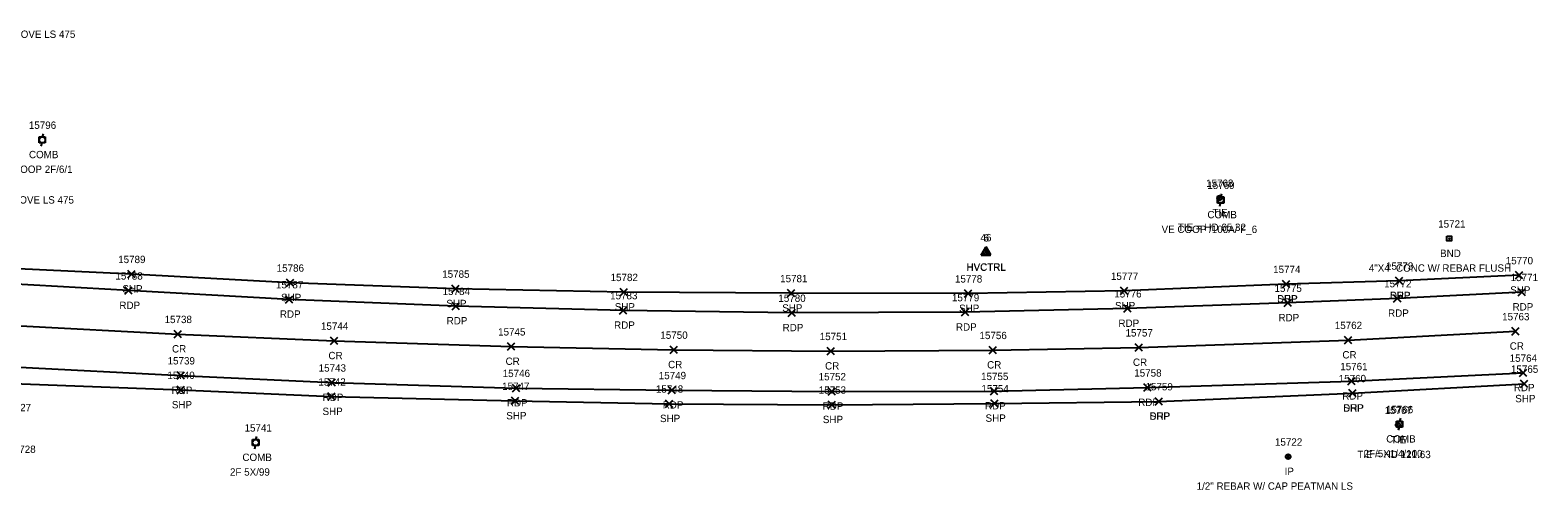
# Model space of a CAD drawing. Extents: x 1606530 to 1613020, y 784959 to 789666.
# Drawn here: x 1609686.4 to 1610096.8, y 788384.4 to 788509.5 of the extents above; entities that cross this region are included whole.
import ezdxf

# ---------------------------------------------------------------- set-up
doc = ezdxf.new("R2010")
doc.units = 0
for name, color, linetype in [('C_A', 7, 'Continuous'), ('C_C', 7, 'Continuous'), ('C_I', 7, 'Continuous'), ('CBP', 7, 'Continuous'), ('CPSM', 7, 'Continuous'), ('L_I', 7, 'Continuous'), ('M_A', 7, 'Continuous'), ('M_C', 7, 'Continuous'), ('M_I', 7, 'Continuous'), ('MHBP', 7, 'Continuous'), ('MPIR', 7, 'Continuous'), ('P_A', 7, 'Continuous'), ('P_I', 7, 'Continuous'), ('P_TIC', 7, 'Continuous'), ('PET', 7, 'Continuous'), ('PRC', 7, 'Continuous'), ('PSP', 7, 'Continuous'), ('R_A', 7, 'Continuous'), ('R_I', 7, 'Continuous'), ('R_TIC', 7, 'Continuous'), ('U_A', 7, 'Continuous'), ('U_C', 7, 'Continuous'), ('U_I', 7, 'Continuous'), ('UP', 7, 'Continuous')]:
    doc.layers.add(name, color=color, linetype=linetype)

msp = doc.modelspace()

# ---------------------------------------------------------------- linework, layer by layer
at = {"layer": 'CBP'}
for centre, radius in [((1610010.15, 788463.87), 0.625), ((1610010.15, 788463.87), 0.0833), ((1610058.75, 788402.03), 0.625), ((1610058.75, 788402.03), 0.0833)]:
    msp.add_circle(centre, radius, dxfattribs=at)
at = {"layer": 'CPSM'}
for p, q in [((1609945.3, 788448.27), (1609946.55, 788450.43)), ((1609945.3, 788448.27), (1609946.55, 788448.99)), ((1609945.3, 788448.27), (1609947.8, 788448.27)), ((1609945.37, 788448.35), (1609946.62, 788450.51)), ((1609945.37, 788448.35), (1609946.62, 788449.07)), ((1609945.37, 788448.35), (1609947.87, 788448.35)), ((1609947.8, 788448.27), (1609946.55, 788450.43)), ((1609946.55, 788448.99), (1609946.55, 788450.43)), ((1609946.55, 788448.99), (1609946.55, 788448.99)), ((1609946.55, 788448.99), (1609947.8, 788448.27)), ((1609947.87, 788448.35), (1609946.62, 788450.51)), ((1609946.62, 788449.07), (1609946.62, 788450.51)), ((1609946.62, 788449.07), (1609946.62, 788449.07)), ((1609946.62, 788449.07), (1609947.87, 788448.35))]:
    msp.add_line(p, q, dxfattribs=at)
at = {"layer": 'MHBP'}
msp.add_lwpolyline([(1610072.09, 788453.41), (1610073.34, 788453.41), (1610073.34, 788452.16), (1610072.09, 788452.16)], close=True, dxfattribs=at)
msp.add_circle((1610072.72, 788452.78), 0.0833, dxfattribs=at)
at = {"layer": 'MPIR'}
msp.add_lwpolyline([(1610028.85, 788393.76), (1610028.56, 788393.26), (1610029.13, 788393.26)], close=True, dxfattribs=at)
msp.add_circle((1610028.85, 788393.43), 0.667, dxfattribs=at)
at = {"layer": 'P_TIC'}
for points in [[(1609712.92, 788442.12), (1609714.92, 788444.12)], [(1609714.92, 788442.12), (1609712.92, 788444.12)], [(1610090.76, 788441.8), (1610092.76, 788443.8)], [(1610092.76, 788441.8), (1610090.76, 788443.8)], [(1609712.17, 788437.63), (1609714.17, 788439.63)], [(1609714.17, 788437.63), (1609712.17, 788439.63)], [(1609756.12, 788439.77), (1609758.12, 788441.77)], [(1609758.12, 788439.77), (1609756.12, 788441.77)], [(1609801.13, 788438.13), (1609803.13, 788440.13)], [(1609803.13, 788438.13), (1609801.13, 788440.13)], [(1609846.97, 788437.22), (1609848.97, 788439.22)], [(1609848.97, 788437.22), (1609846.97, 788439.22)], [(1609892.56, 788436.91), (1609894.56, 788438.91)], [(1609894.56, 788436.91), (1609892.56, 788438.91)], [(1609940.73, 788436.83), (1609942.73, 788438.83)], [(1609942.73, 788436.83), (1609940.73, 788438.83)], [(1609983.18, 788437.55), (1609985.18, 788439.55)], [(1609985.18, 788437.55), (1609983.18, 788439.55)], [(1610027.34, 788439.41), (1610029.34, 788441.41)], [(1610029.34, 788439.41), (1610027.34, 788441.41)], [(1610058.07, 788440.32), (1610060.07, 788442.32)], [(1610060.07, 788440.32), (1610058.07, 788442.32)], [(1610091.45, 788437.22), (1610093.45, 788439.22)], [(1610093.45, 788437.22), (1610091.45, 788439.22)], [(1609755.86, 788435.25), (1609757.86, 788437.25)], [(1609757.86, 788435.25), (1609755.86, 788437.25)], [(1609801.26, 788433.44), (1609803.26, 788435.44)], [(1609803.26, 788433.44), (1609801.26, 788435.44)], [(1609984.15, 788432.76), (1609986.15, 788434.76)], [(1609986.15, 788432.76), (1609984.15, 788434.76)], [(1610027.72, 788434.28), (1610029.72, 788436.28)], [(1610029.72, 788434.28), (1610027.72, 788436.28)], [(1610057.57, 788435.52), (1610059.57, 788437.52)], [(1610059.57, 788435.52), (1610057.57, 788437.52)], [(1609846.84, 788432.26), (1609848.84, 788434.26)], [(1609848.84, 788432.26), (1609846.84, 788434.26)], [(1609892.72, 788431.57), (1609894.72, 788433.57)], [(1609894.72, 788431.57), (1609892.72, 788433.57)], [(1609939.91, 788431.73), (1609941.91, 788433.73)], [(1609941.91, 788431.73), (1609939.91, 788433.73)], [(1609725.55, 788425.79), (1609727.55, 788427.79)], [(1609727.55, 788425.79), (1609725.55, 788427.79)], [(1610089.74, 788426.55), (1610091.74, 788428.55)], [(1610091.74, 788426.55), (1610089.74, 788428.55)], [(1609768.12, 788423.96), (1609770.12, 788425.96)], [(1609770.12, 788423.96), (1609768.12, 788425.96)], [(1609816.35, 788422.41), (1609818.35, 788424.41)], [(1609818.35, 788422.41), (1609816.35, 788424.41)], [(1609860.6, 788421.51), (1609862.6, 788423.51)], [(1609862.6, 788421.51), (1609860.6, 788423.51)], [(1609903.34, 788421.15), (1609905.34, 788423.15)], [(1609905.34, 788421.15), (1609903.34, 788423.15)], [(1609947.45, 788421.43), (1609949.45, 788423.43)], [(1609949.45, 788421.43), (1609947.45, 788423.43)], [(1609987.16, 788422.14), (1609989.16, 788424.14)], [(1609989.16, 788422.14), (1609987.16, 788424.14)], [(1610044.18, 788424.17), (1610046.18, 788426.17)], [(1610046.18, 788424.17), (1610044.18, 788426.17)], [(1609726.38, 788414.53), (1609728.38, 788416.53)], [(1609728.38, 788414.53), (1609726.38, 788416.53)], [(1609767.5, 788412.58), (1609769.5, 788414.58)], [(1609769.5, 788412.58), (1609767.5, 788414.58)], [(1610045.1, 788412.97), (1610047.1, 788414.97)], [(1610047.1, 788412.97), (1610045.1, 788414.97)], [(1610091.79, 788415.25), (1610093.79, 788417.25)], [(1610093.79, 788415.25), (1610091.79, 788417.25)], [(1610092.14, 788412.25), (1610094.14, 788414.25)], [(1610094.14, 788412.25), (1610092.14, 788414.25)], [(1609726.4, 788410.58), (1609728.4, 788412.58)], [(1609728.4, 788410.58), (1609726.4, 788412.58)], [(1609767.42, 788408.77), (1609769.42, 788410.77)], [(1609769.42, 788408.77), (1609767.42, 788410.77)], [(1609817.65, 788411.1), (1609819.65, 788413.1)], [(1609819.65, 788411.1), (1609817.65, 788413.1)], [(1609860.08, 788410.52), (1609862.08, 788412.52)], [(1609862.08, 788410.52), (1609860.08, 788412.52)], [(1609903.62, 788410.21), (1609905.62, 788412.21)], [(1609905.62, 788410.21), (1609903.62, 788412.21)], [(1609947.83, 788410.28), (1609949.83, 788412.28)], [(1609949.83, 788410.28), (1609947.83, 788412.28)], [(1609989.54, 788411.23), (1609991.54, 788413.23)], [(1609991.54, 788411.23), (1609989.54, 788413.23)], [(1610045.33, 788409.69), (1610047.33, 788411.69)], [(1610047.33, 788409.69), (1610045.33, 788411.69)], [(1609817.44, 788407.59), (1609819.44, 788409.59)], [(1609819.44, 788407.59), (1609817.44, 788409.59)], [(1609859.3, 788406.84), (1609861.3, 788408.84)], [(1609861.3, 788406.84), (1609859.3, 788408.84)], [(1609903.64, 788406.56), (1609905.64, 788408.56)], [(1609905.64, 788406.56), (1609903.64, 788408.56)], [(1609947.94, 788406.93), (1609949.94, 788408.93)], [(1609949.94, 788406.93), (1609947.94, 788408.93)], [(1609992.61, 788407.48), (1609994.61, 788409.48)], [(1609994.61, 788407.48), (1609992.61, 788409.48)]]:
    msp.add_lwpolyline(points, dxfattribs=at)
at = {"layer": 'PET'}
for points in [[(1610092.45, 788438.22), (1610058.57, 788436.52), (1610028.72, 788435.28), (1609985.15, 788433.76), (1609940.91, 788432.73), (1609893.72, 788432.57), (1609847.84, 788433.26), (1609802.26, 788434.44), (1609756.86, 788436.25), (1609713.17, 788438.63), (1609680.93, 788440.45)], [(1609681.7, 788417.92), (1609727.38, 788415.53), (1609768.5, 788413.58), (1609818.65, 788412.1), (1609861.08, 788411.52), (1609904.62, 788411.21), (1609948.83, 788411.28), (1609990.54, 788412.23), (1610046.1, 788413.97), (1610092.79, 788416.25)]]:
    msp.add_lwpolyline(points, dxfattribs=at)
at = {"layer": 'PRC'}
msp.add_lwpolyline([(1609682.03, 788429.15), (1609726.55, 788426.79), (1609769.12, 788424.96), (1609817.35, 788423.41), (1609861.6, 788422.51), (1609904.34, 788422.15), (1609948.45, 788422.43), (1609988.16, 788423.14), (1610045.18, 788425.17), (1610090.74, 788427.55)], dxfattribs=at)
at = {"layer": 'PSP'}
for points in [[(1610091.76, 788442.8), (1610059.07, 788441.32), (1610028.34, 788440.41), (1609984.18, 788438.55), (1609941.73, 788437.83), (1609893.56, 788437.91), (1609847.97, 788438.22), (1609802.13, 788439.13), (1609757.12, 788440.77), (1609713.92, 788443.12), (1609681.22, 788444.65)], [(1609681.63, 788413.32), (1609727.4, 788411.58), (1609768.42, 788409.77), (1609818.44, 788408.59), (1609860.3, 788407.84), (1609904.64, 788407.56), (1609948.94, 788407.93), (1609993.61, 788408.48), (1610046.33, 788410.69), (1610093.14, 788413.25)]]:
    msp.add_lwpolyline(points, dxfattribs=at)
at = {"layer": 'R_TIC'}
for points in [[(1610027.34, 788439.41), (1610029.34, 788441.41)], [(1610029.34, 788439.41), (1610027.34, 788441.41)], [(1610058.07, 788440.32), (1610060.07, 788442.32)], [(1610060.07, 788440.32), (1610058.07, 788442.32)], [(1610045.33, 788409.69), (1610047.33, 788411.69)], [(1610047.33, 788409.69), (1610045.33, 788411.69)], [(1609992.61, 788407.48), (1609994.61, 788409.48)], [(1609994.61, 788407.48), (1609992.61, 788409.48)]]:
    msp.add_lwpolyline(points, dxfattribs=at)
at = {"layer": 'UP'}
for p, q in [((1609688.81, 788478.84), (1609688.81, 788480.5)), ((1609688.81, 788480.5), (1609690.48, 788480.5)), ((1609689.9, 788481.34), (1609689.65, 788480.5)), ((1609689.65, 788479.67), (1609689.65, 788479.67)), ((1609690.48, 788480.5), (1609690.48, 788478.84)), ((1609690.48, 788478.84), (1609688.81, 788478.84)), ((1609689.4, 788478), (1609689.65, 788478.84)), ((1610009.64, 788462.48), (1610009.64, 788464.15)), ((1610009.64, 788464.15), (1610011.3, 788464.15)), ((1610010.72, 788464.98), (1610010.47, 788464.15)), ((1610010.47, 788463.32), (1610010.47, 788463.32)), ((1610011.3, 788464.15), (1610011.3, 788462.48)), ((1610011.3, 788462.48), (1610009.64, 788462.48)), ((1610010.22, 788461.65), (1610010.47, 788462.48)), ((1610058.32, 788401.43), (1610058.32, 788403.1)), ((1610058.32, 788403.1), (1610059.99, 788403.1)), ((1610059.41, 788403.93), (1610059.16, 788403.1)), ((1610059.16, 788402.27), (1610059.16, 788402.27)), ((1610059.99, 788403.1), (1610059.99, 788401.43)), ((1609746.92, 788396.43), (1609746.92, 788398.09)), ((1609746.92, 788398.09), (1609748.59, 788398.09)), ((1609748, 788398.93), (1609747.75, 788398.09)), ((1609748.59, 788398.09), (1609748.59, 788396.43)), ((1610059.99, 788401.43), (1610058.32, 788401.43)), ((1610058.91, 788400.6), (1610059.16, 788401.43)), ((1609748.59, 788396.43), (1609746.92, 788396.43)), ((1609747.5, 788395.59), (1609747.75, 788396.43)), ((1609747.75, 788397.26), (1609747.75, 788397.26))]:
    msp.add_line(p, q, dxfattribs=at)
for centre in [(1609689.65, 788479.67), (1610010.47, 788463.32), (1610059.16, 788402.27), (1609747.75, 788397.26)]:
    msp.add_circle(centre, 0.833, dxfattribs=at)

# ---------------------------------------------------------------- texts
at = {"layer": 'C_A'}
for s, p in [('TIE', (1610008.23, 788458.87)), ('HVCTRL', (1609941.24, 788443.99)), ('HVCTRL', (1609941.32, 788444.07)), ('TIE', (1610056.83, 788397.03))]:
    msp.add_text(s, height=2, dxfattribs=at).set_placement(p)
at = {"layer": 'C_C'}
for s, p in [('TIE = HD 65.32', (1609998.83, 788454.87)), ('TIE = HD 121.63', (1610047.67, 788393.03))]:
    msp.add_text(s, height=2, dxfattribs=at).set_placement(p)
at = {"layer": 'C_I'}
for s, p in [('15768', (1610006.51, 788466.87)), ('46', (1609945.1, 788452.07)), ('6', (1609945.93, 788451.99)), ('15767', (1610055.12, 788405.03))]:
    msp.add_text(s, height=2, dxfattribs=at).set_placement(p)
at = {"layer": 'L_I'}
for s, p in [('15727', (1609679.18, 788405.8)), ('15728', (1609680.42, 788394.45))]:
    msp.add_text(s, height=2, dxfattribs=at).set_placement(p)
at = {"layer": 'M_A'}
for s, p in [('BND', (1610070.21, 788447.78)), ('IP', (1610027.89, 788388.43))]:
    msp.add_text(s, height=2, dxfattribs=at).set_placement(p)
at = {"layer": 'M_C'}
for s, p in [('3/4" REBAR W/ CAP GOVE LS 475', (1609656.09, 788507.43)), ('3/4" REBAR W/ CAP GOVE LS 475', (1609655.71, 788462.33)), ('4"X4" CONC W/ REBAR FLUSH', (1610050.8, 788443.78)), ('1/2" REBAR W/ CAP PEATMAN LS', (1610003.93, 788384.43))]:
    msp.add_text(s, height=2, dxfattribs=at).set_placement(p)
at = {"layer": 'M_I'}
for s, p in [('15721', (1610069.69, 788455.78)), ('15722', (1610025.25, 788396.43))]:
    msp.add_text(s, height=2, dxfattribs=at).set_placement(p)
at = {"layer": 'P_A'}
for s, p in [('SHP', (1609711.46, 788438.12)), ('SHP', (1610089.3, 788437.8)), ('RDP', (1609710.65, 788433.63)), ('SHP', (1609754.66, 788435.77)), ('SHP', (1609799.66, 788434.13)), ('SHP', (1609845.51, 788433.22)), ('SHP', (1609891.1, 788432.91)), ('SHP', (1609939.26, 788432.83)), ('SHP', (1609981.71, 788433.55)), ('SHP', (1610025.87, 788435.41)), ('SHP', (1610056.6, 788436.32)), ('RDP', (1610089.94, 788433.22)), ('RDP', (1609754.34, 788431.25)), ('RDP', (1609799.74, 788429.44)), ('RDP', (1609982.64, 788428.76)), ('RDP', (1610026.21, 788430.28)), ('RDP', (1610056.05, 788431.52)), ('RDP', (1609845.33, 788428.26)), ('RDP', (1609891.21, 788427.57)), ('RDP', (1609938.4, 788427.73)), ('CR', (1609724.98, 788421.79)), ('CR', (1610043.61, 788420.17)), ('CR', (1610089.17, 788422.55)), ('CR', (1609767.56, 788419.96)), ('CR', (1609815.79, 788418.41)), ('CR', (1609860.04, 788417.51)), ('CR', (1609902.77, 788417.15)), ('CR', (1609946.89, 788417.43)), ('CR', (1609986.59, 788418.14)), ('RDP', (1609724.87, 788410.53)), ('RDP', (1609765.99, 788408.58)), ('RDP', (1610043.58, 788408.97)), ('RDP', (1610090.28, 788411.25)), ('SHP', (1610090.67, 788408.25)), ('SHP', (1609724.93, 788406.58)), ('SHP', (1609765.95, 788404.77)), ('RDP', (1609816.14, 788407.1)), ('RDP', (1609858.57, 788406.52)), ('RDP', (1609902.11, 788406.21)), ('RDP', (1609946.31, 788406.28)), ('RDP', (1609988.03, 788407.23)), ('SHP', (1610043.87, 788405.69)), ('SHP', (1609815.98, 788403.59)), ('SHP', (1609857.84, 788402.84)), ('SHP', (1609902.17, 788402.56)), ('SHP', (1609946.47, 788402.93)), ('SHP', (1609991.15, 788403.48))]:
    msp.add_text(s, height=2, dxfattribs=at).set_placement(p)
at = {"layer": 'P_I'}
for s, p in [('15789', (1609710.32, 788446.12)), ('15770', (1610088.08, 788445.8)), ('15788', (1609709.57, 788441.63)), ('15786', (1609753.48, 788443.77)), ('15785', (1609798.54, 788442.13)), ('15782', (1609844.38, 788441.22)), ('15781', (1609890.54, 788440.91)), ('15778', (1609938.13, 788440.83)), ('15777', (1609980.59, 788441.55)), ('15774', (1610024.75, 788443.41)), ('15773', (1610055.48, 788444.32)), ('15771', (1610089.43, 788441.22)), ('15787', (1609753.27, 788439.25)), ('15784', (1609798.66, 788437.44)), ('15776', (1609981.51, 788436.76)), ('15775', (1610025.13, 788438.28)), ('15772', (1610054.98, 788439.52)), ('15783', (1609844.25, 788436.26)), ('15780', (1609890.05, 788435.57)), ('15779', (1609937.31, 788435.73)), ('15738', (1609722.96, 788429.79)), ('15763', (1610087.1, 788430.55)), ('15744', (1609765.53, 788427.96)), ('15745', (1609813.76, 788426.41)), ('15750', (1609857.93, 788425.51)), ('15751', (1609901.32, 788425.15)), ('15756', (1609944.81, 788425.43)), ('15757', (1609984.57, 788426.14)), ('15762', (1610041.54, 788428.17)), ('15739', (1609723.78, 788418.53)), ('15743', (1609764.91, 788416.58)), ('15761', (1610043.03, 788416.97)), ('15764', (1610089.16, 788419.25)), ('15765', (1610089.5, 788416.25)), ('15740', (1609723.72, 788414.58)), ('15742', (1609764.83, 788412.77)), ('15746', (1609815.01, 788415.1)), ('15749', (1609857.49, 788414.52)), ('15752', (1609901.03, 788414.21)), ('15755', (1609945.24, 788414.28)), ('15758', (1609986.95, 788415.23)), ('15760', (1610042.61, 788413.69)), ('15747', (1609814.85, 788411.59)), ('15748', (1609856.71, 788410.84)), ('15753', (1609901.05, 788410.56)), ('15754', (1609945.34, 788410.93)), ('15759', (1609990.01, 788411.48))]:
    msp.add_text(s, height=2, dxfattribs=at).set_placement(p)
at = {"layer": 'R_A'}
for p in [(1610025.83, 788435.41), (1610056.55, 788436.32), (1610043.82, 788405.69), (1609991.1, 788403.48)]:
    msp.add_text('DRP', height=2, dxfattribs=at).set_placement(p)
at = {"layer": 'R_I'}
for s, p in [('15774', (1610024.75, 788443.41)), ('15773', (1610055.48, 788444.32)), ('15760', (1610042.61, 788413.69)), ('15759', (1609990.01, 788411.48))]:
    msp.add_text(s, height=2, dxfattribs=at).set_placement(p)
at = {"layer": 'U_A'}
for p in [(1609686.03, 788474.67), (1610006.86, 788458.32), (1610055.54, 788397.27), (1609744.14, 788392.26)]:
    msp.add_text('COMB', height=2, dxfattribs=at).set_placement(p)
at = {"layer": 'U_C'}
for s, p in [('VE COOP 2F/6/1', (1609677.4, 788470.67)), ('VE COOP /100A/ F_6', (1609994.39, 788454.32)), ('2F/5X1/4/100', (1610049.38, 788393.27)), ('2F 5X/99', (1609740.76, 788388.26))]:
    msp.add_text(s, height=2, dxfattribs=at).set_placement(p)
at = {"layer": 'U_I'}
for s, p in [('15796', (1609686, 788482.67)), ('15769', (1610006.83, 788466.32)), ('15766', (1610055.46, 788405.27)), ('15741', (1609744.73, 788400.26))]:
    msp.add_text(s, height=2, dxfattribs=at).set_placement(p)

doc.saveas('drawing.dxf')
